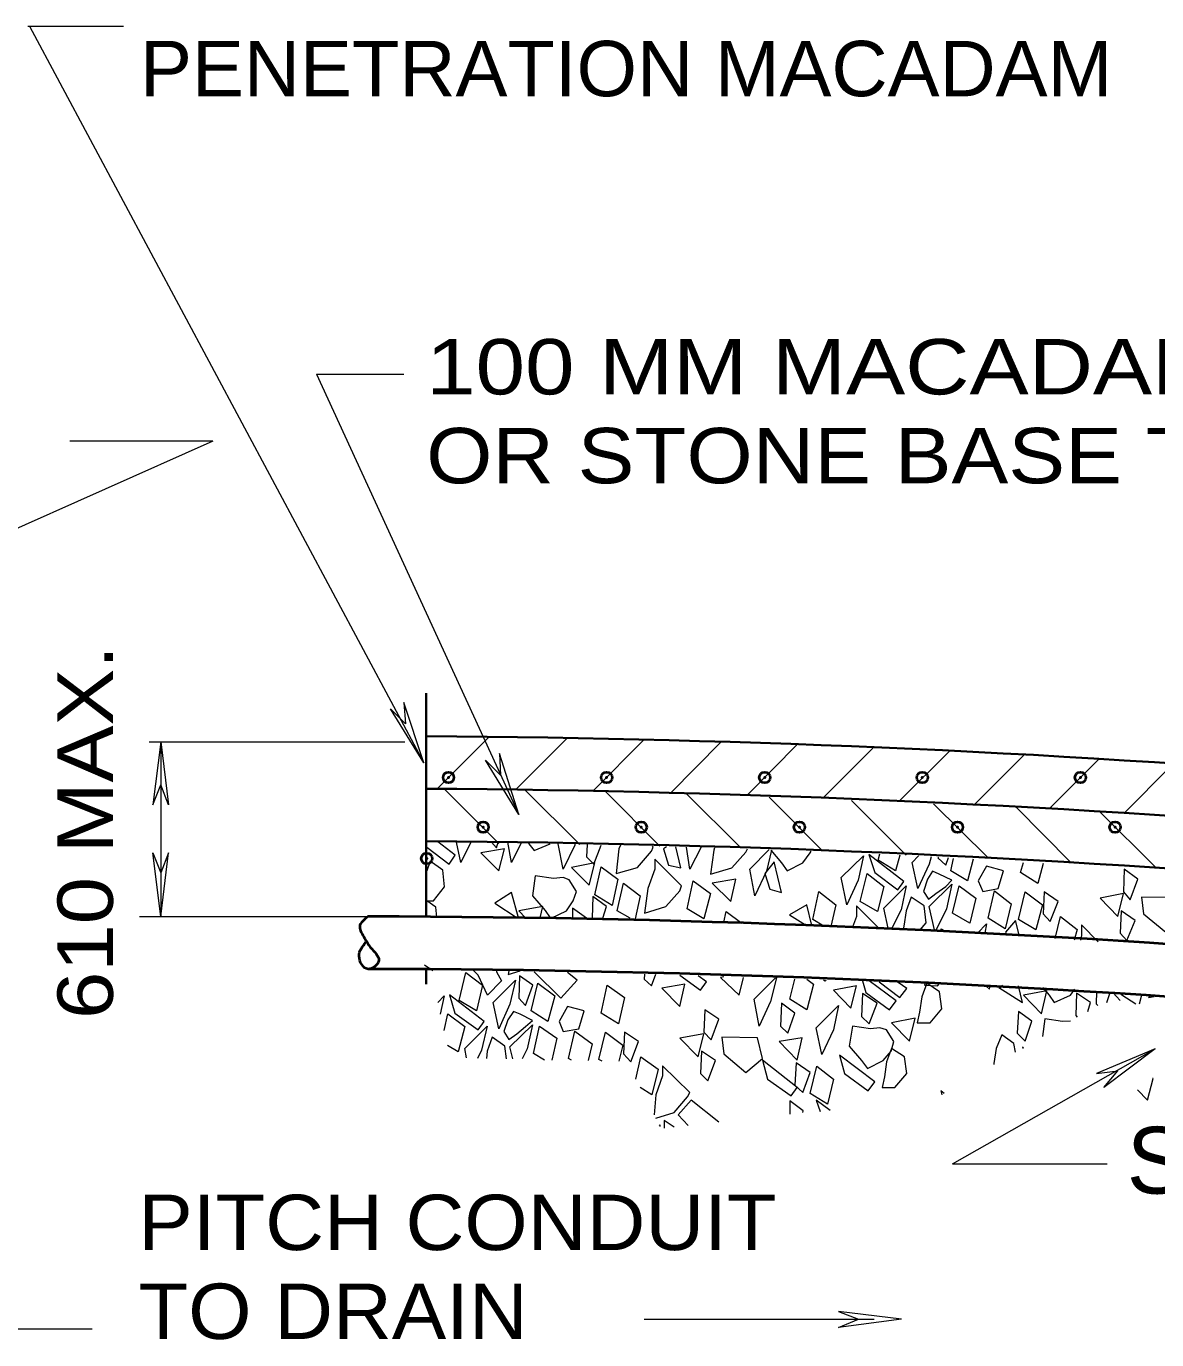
# Model space of a CAD drawing. Extents: x 312583 to 312854, y 144419 to 144597.
# Drawn here: x 312670 to 312685.51, y 144438.89 to 144456.92 of the extents above; entities that cross this region are included whole.
import ezdxf

# ---------------------------------------------------------------- set-up
doc = ezdxf.new("R2010")
doc.units = 0
doc.header["$LTSCALE"] = 0.3
doc.header["$PDMODE"] = 32
doc.header["$PDSIZE"] = 0.15
doc.layers.add('1', color=7, linetype='Continuous', lineweight=40)
doc.layers.add('2', color=7, linetype='Continuous', lineweight=13)

msp = doc.modelspace()

# ---------------------------------------------------------------- linework, layer by layer
at = {"layer": '1', "lineweight": 13}
for p, q in [((312675.6388, 144446.4551), (312676.3365, 144447.1527)), ((312676.7122, 144446.4397), (312677.4252, 144447.1527)), ((312677.7778, 144446.4244), (312678.4755, 144447.1297)), ((312678.8358, 144446.3937), (312679.5335, 144447.0991)), ((312679.8938, 144446.3707), (312680.5838, 144447.0684)), ((312680.9365, 144446.3324), (312681.6265, 144447.0224)), ((312681.9792, 144446.2864), (312682.6692, 144446.9764)), ((312683.0065, 144446.2327), (312683.6965, 144446.9227)), ((312684.0415, 144446.1867), (312684.7162, 144446.8614)), ((312685.0612, 144446.1177), (312685.7052, 144446.7617)), ((312675.7385, 144446.4474), (312676.4822, 144445.7037)), ((312676.8425, 144446.4321), (312677.5938, 144445.6884)), ((312677.9465, 144446.4167), (312678.6902, 144445.6654)), ((312679.0582, 144446.3861), (312679.7942, 144445.6501)), ((312680.1928, 144446.3401), (312680.9212, 144445.6041)), ((312681.3198, 144446.2941), (312682.0712, 144445.5427)), ((312682.4468, 144446.2481), (312683.1905, 144445.5121)), ((312683.5815, 144446.2021), (312684.3328, 144445.4431)), ((312684.7238, 144446.1407), (312685.4982, 144445.3741)), ((312676.8885, 144445.7114), (312676.8962, 144445.6961)), ((312678.7822, 144445.6577), (312678.7438, 144445.6271)), ((312679.9245, 144445.3511), (312680.1928, 144445.6194)), ((312680.2158, 144445.6117), (312680.3615, 144445.4354)), ((312675.4932, 144445.4891), (312675.4932, 144445.4967)), ((312675.5392, 144445.4584), (312675.4932, 144445.3281)), ((312681.6878, 144445.4737), (312681.7108, 144445.5581)), ((312682.1555, 144445.4431), (312682.2398, 144445.5351)), ((312682.6845, 144445.3281), (312682.7228, 144445.4967)), ((312683.6428, 144445.3051), (312683.6812, 144445.4431)), ((312676.4285, 144444.8834), (312676.7352, 144444.6841)), ((312677.7702, 144444.9754), (312677.7625, 144444.6764)), ((312676.7582, 144444.7761), (312676.8502, 144444.6841)), ((312677.1185, 144444.7837), (312677.1875, 144444.6841)), ((312677.4942, 144444.8144), (312677.4942, 144444.6764)), ((312677.6858, 144444.6764), (312677.4942, 144444.8144)), ((312678.2838, 144444.6764), (312678.1075, 144444.7761)), ((312680.4688, 144444.7224), (312680.6912, 144444.5844)), ((312681.3888, 144444.6994), (312681.3352, 144444.5537)), ((312681.8258, 144444.5384), (312681.7645, 144444.8144)), ((312682.4622, 144444.5154), (312682.3855, 144444.8374)), ((312680.9442, 144444.5691), (312680.7908, 144444.6611)), ((312683.4358, 144444.4847), (312683.4512, 144444.4464)), ((312684.4785, 144444.4387), (312684.4632, 144444.3774)), ((312675.5775, 144443.9557), (312675.4625, 144444.0324)), ((312684.9078, 144443.6567), (312685.0075, 144443.5494))]:
    msp.add_line(p, q, dxfattribs=at)
for points in [[(312675.4855, 144445.6577), (312675.4932, 144445.6501), (312675.7998, 144445.4201), (312675.8842, 144445.5427), (312675.6465, 144445.7267)], [(312676.0988, 144445.7191), (312675.9608, 144445.4431), (312675.8995, 144445.7191)], [(312676.3825, 144445.7191), (312676.4515, 144445.6424), (312676.4745, 144445.7191)], [(312676.7888, 144445.7114), (312676.6585, 144445.4431), (312676.6048, 144445.7191)], [(312676.8962, 144445.6961), (312676.9652, 144445.6041), (312677.1875, 144445.6961)], [(312677.5248, 144445.6961), (312677.5248, 144445.6807), (312677.3638, 144445.3511), (312677.2948, 144445.6961)], [(312677.6935, 144445.6884), (312677.6858, 144445.5197), (312677.7855, 144445.4201), (312677.8852, 144445.6807)], [(312678.1535, 144445.6807), (312678.1305, 144445.6271), (312678.0922, 144445.2897), (312678.3835, 144445.3741), (312678.5752, 144445.5964), (312678.5982, 144445.6501), (312678.5905, 144445.6654)], [(312678.7438, 144445.6271), (312678.8128, 144445.4047), (312678.9815, 144445.3664), (312678.9125, 144445.6577)], [(312679.2575, 144445.6501), (312679.1042, 144445.3511), (312679.0582, 144445.6501)], [(312679.4415, 144445.6424), (312679.4338, 144445.6117), (312679.3878, 144445.2821), (312679.6792, 144445.3664), (312679.8708, 144445.5811), (312679.8938, 144445.6271)], [(312680.2235, 144445.6117), (312680.1545, 144445.3204), (312679.9935, 144444.9831), (312679.9245, 144445.3511)], [(312680.3615, 144445.4354), (312680.4382, 144445.3281), (312680.6528, 144445.4354), (312680.7525, 144445.5734), (312680.7678, 144445.5964)], [(312675.4932, 144444.9141), (312675.5852, 144444.9141), (312675.7385, 144445.1057), (312675.7155, 144445.3357), (312675.5392, 144445.4584)], [(312681.9868, 144445.5427), (312681.9255, 144445.3281), (312681.6878, 144445.4737)], [(312682.4162, 144445.5197), (312682.3855, 144445.4201), (312682.2322, 144445.0827), (312682.1555, 144445.4431)], [(312682.5158, 144445.5121), (312682.5082, 144445.5044), (312682.6155, 144445.4047), (312682.6538, 144445.5121)], [(312682.9912, 144445.4891), (312682.9145, 144445.1901), (312682.6845, 144445.3281)], [(312683.9495, 144445.4277), (312683.8805, 144445.1517), (312683.6428, 144445.3051)], [(312677.2028, 144444.6764), (312677.4098, 144444.7761), (312677.5018, 144444.9141), (312677.5478, 144445.0444), (312677.4482, 144445.2054), (312677.3638, 144445.2361), (312677.2335, 144445.2207), (312676.9805, 144445.2591), (312676.9422, 144444.9831), (312677.1185, 144444.7837)], [(312678.1075, 144444.7761), (312678.1918, 144445.1594), (312678.4218, 144444.9831), (312678.3528, 144444.6687)], [(312681.7645, 144444.8144), (312682.0712, 144445.1211), (312682.0022, 144444.7914), (312681.8718, 144444.5307)], [(312682.3855, 144444.8374), (312682.6998, 144445.1441), (312682.6232, 144444.8067), (312682.4852, 144444.5154)], [(312675.6312, 144444.6917), (312675.6158, 144444.8297), (312675.4932, 144444.9141)], [(312676.7505, 144444.6841), (312676.6585, 144445.0291), (312676.4285, 144444.8834)], [(312677.9082, 144444.6764), (312677.9618, 144444.8374), (312677.7702, 144444.9754)], [(312680.7908, 144444.6611), (312680.8752, 144445.0444), (312681.1052, 144444.8604), (312681.0362, 144444.5614)], [(312682.1402, 144444.9677), (312682.0712, 144444.7761), (312682.0405, 144444.5691), (312682.0328, 144444.5231)], [(312682.2628, 144444.5154), (312682.3472, 144444.6151), (312682.3165, 144444.8451), (312682.1402, 144444.9677)], [(312677.0495, 144444.6841), (312677.0878, 144444.8374), (312676.7582, 144444.7761)], [(312679.5718, 144444.6227), (312679.6025, 144444.7684), (312679.8172, 144444.6074)], [(312680.7755, 144444.5767), (312680.7065, 144444.8604), (312680.4688, 144444.7224)], [(312681.6955, 144444.5384), (312681.3888, 144444.8451), (312681.3888, 144444.6994)], [(312684.1182, 144444.4004), (312684.1872, 144444.6994), (312684.4172, 144444.5231), (312684.3788, 144444.3774)], [(312682.5542, 144444.5077), (312682.5542, 144444.5307), (312682.5925, 144444.5077)], [(312683.0525, 144444.4694), (312683.1752, 144444.5997), (312683.1522, 144444.4694)], [(312683.6275, 144444.4311), (312683.5738, 144444.6457), (312683.4358, 144444.4847)], [(312684.7085, 144444.3544), (312684.4785, 144444.5844), (312684.4785, 144444.4387)]]:
    msp.add_lwpolyline(points, dxfattribs=at)
for points in [[(312676.2368, 144445.5734), (312676.4822, 144445.3281), (312676.5588, 144445.6271)], [(312677.4788, 144445.3741), (312677.7242, 144445.1287), (312677.8008, 144445.4354)], [(312678.6212, 144445.3511), (312678.5292, 144445.0827), (312678.4832, 144444.7454), (312678.7745, 144444.8374), (312678.9662, 144445.0521), (312678.9892, 144445.1211), (312678.6212, 144445.4891)], [(312680.1315, 144445.2897), (312680.2005, 144445.0751), (312680.3615, 144445.0291), (312680.2618, 144445.4507)], [(312681.1818, 144445.2361), (312681.4885, 144445.5351), (312681.4118, 144445.1977), (312681.2585, 144444.8604)], [(312681.6418, 144445.3051), (312681.9562, 144445.0674), (312682.0405, 144445.1824), (312681.5575, 144445.5504)], [(312677.8008, 144444.9984), (312677.8852, 144445.3817), (312678.1152, 144445.2131), (312678.0385, 144444.8527)], [(312681.4425, 144444.9064), (312681.5345, 144445.2897), (312681.7645, 144445.1134), (312681.6802, 144444.7684)], [(312682.5235, 144445.2821), (312682.4315, 144445.3204), (312682.3625, 144445.2131), (312682.3088, 144445.0444), (312682.3778, 144444.9371), (312682.4775, 144445.0137), (312682.6155, 144445.1134), (312682.6998, 144445.1977)], [(312683.1752, 144445.3894), (312683.0602, 144445.1901), (312683.1215, 144445.0444), (312683.3362, 144445.0827), (312683.4052, 144445.3281)], [(312685.0612, 144445.3511), (312685.0535, 144445.0367), (312685.1455, 144444.9294), (312685.2528, 144445.2131)], [(312679.0658, 144444.8067), (312679.1502, 144445.1901), (312679.3878, 144445.0137), (312679.2958, 144444.6687)], [(312679.4108, 144445.1594), (312679.6638, 144444.9064), (312679.7328, 144445.2131)], [(312682.7075, 144444.7454), (312682.7995, 144445.1211), (312683.0295, 144444.9524), (312682.9452, 144444.6074)], [(312683.1982, 144444.6764), (312683.2825, 144445.0521), (312683.5125, 144444.8757), (312683.4282, 144444.5307)], [(312683.6122, 144444.6611), (312683.7042, 144445.0367), (312683.9418, 144444.8604), (312683.8498, 144444.5154)], [(312683.9648, 144445.0367), (312683.9495, 144444.7377), (312684.0492, 144444.6304), (312684.1565, 144444.9064)], [(312684.7315, 144444.9524), (312684.9768, 144444.6994), (312685.0535, 144445.0137)], [(312685.3295, 144444.7377), (312685.6362, 144444.4847), (312685.8508, 144444.6764), (312685.7895, 144444.9601), (312685.2988, 144444.9677)], [(312685.0228, 144444.7761), (312685.0075, 144444.4694), (312685.0995, 144444.3697), (312685.2145, 144444.6457)]]:
    msp.add_lwpolyline(points, close=True, dxfattribs=at)
at = {"layer": '1'}
for p in [(312675.7922, 144446.6084), (312677.9618, 144446.6084), (312680.1315, 144446.6084), (312682.2935, 144446.6084), (312684.4632, 144446.6084), (312676.2675, 144445.9261), (312678.4372, 144445.9261), (312680.6068, 144445.9261), (312682.7765, 144445.9261), (312684.9385, 144445.9261), (312675.4932, 144445.4967)]:
    msp.add_point(p, dxfattribs=at)
at = {"layer": '2'}
for p, q in [((312670.0192, 144456.9201), (312671.3302, 144456.9201)), ((312670.0422, 144456.9201), (312675.4548, 144446.8077)), ((312673.9828, 144452.1437), (312675.1788, 144452.1437)), ((312673.9828, 144452.1437), (312676.7582, 144446.1024)), ((312672.5568, 144451.2237), (312661.0875, 144446.1177)), ((312672.5568, 144451.2237), (312670.5942, 144451.2237)), ((312675.1788, 144447.6357), (312675.2018, 144447.3444)), ((312675.4548, 144446.8077), (312675.1788, 144447.6357)), ((312674.9948, 144447.5514), (312675.2018, 144447.3444)), ((312675.4548, 144446.8077), (312674.9948, 144447.5514)), ((312671.6828, 144447.0991), (312675.1942, 144447.0991)), ((312671.8438, 144447.0991), (312671.7365, 144446.2327)), ((312671.8438, 144447.0991), (312671.8438, 144444.6994)), ((312671.8438, 144447.0991), (312671.9512, 144446.2327)), ((312676.4898, 144446.9381), (312676.5052, 144446.6391)), ((312676.7582, 144446.1024), (312676.4898, 144446.9381)), ((312676.2982, 144446.8461), (312676.5052, 144446.6391)), ((312676.7582, 144446.1024), (312676.2982, 144446.8461)), ((312671.7365, 144446.2327), (312671.8438, 144446.5087)), ((312671.9512, 144446.2327), (312671.8438, 144446.5087)), ((312671.7365, 144445.5734), (312671.8438, 144445.2974)), ((312671.8438, 144444.6994), (312671.7365, 144445.5734)), ((312671.9512, 144445.5734), (312671.8438, 144445.2974)), ((312671.8438, 144444.6994), (312671.9512, 144445.5734)), ((312671.5525, 144444.6994), (312675.1635, 144444.6994)), ((312679.5718, 144443.8714), (312679.5258, 144443.8637)), ((312679.9858, 144443.5647), (312680.2772, 144443.8561)), ((312680.4765, 144443.5647), (312680.5455, 144443.8407)), ((312681.4732, 144443.8177), (312681.5192, 144443.6567)), ((312683.9418, 144443.7257), (312684.0338, 144443.6184)), ((312684.8235, 144443.5187), (312684.8695, 144443.6567)), ((312685.0305, 144443.6184), (312685.0305, 144443.6414)), ((312685.2222, 144443.4957), (312685.0305, 144443.6184)), ((312685.2988, 144443.6184), (312685.2682, 144443.4957)), ((312676.0375, 144442.7597), (312676.0145, 144442.8901)), ((312676.6738, 144442.7444), (312676.6355, 144442.9131)), ((312682.7075, 144441.3031), (312685.4905, 144442.8824)), ((312683.6658, 144442.9054), (312683.6735, 144442.8901)), ((312683.6812, 144442.8977), (312683.6658, 144442.9054)), ((312685.4905, 144442.8824), (312684.6855, 144442.5451)), ((312685.4905, 144442.8824), (312684.7852, 144442.3534)), ((312677.1108, 144442.7291), (312676.9575, 144442.8211)), ((312677.4788, 144442.7291), (312677.4405, 144442.7521)), ((312677.9005, 144442.7137), (312677.8545, 144442.7367)), ((312684.6855, 144442.5451), (312684.9768, 144442.5834)), ((312684.7852, 144442.3534), (312684.9768, 144442.5834)), ((312679.5028, 144441.8781), (312679.1195, 144442.1771)), ((312680.4765, 144442.1694), (312680.4765, 144441.9854)), ((312678.7515, 144441.9011), (312678.7515, 144441.7937)), ((312678.8895, 144441.8091), (312678.7515, 144441.9011)), ((312682.7075, 144441.3031), (312684.8312, 144441.3031)), ((312681.1435, 144439.2791), (312681.4195, 144439.1717)), ((312682.0098, 144439.1717), (312681.1435, 144439.2791)), ((312678.4755, 144439.1717), (312681.6342, 144439.1717)), ((312681.1435, 144439.0567), (312681.4195, 144439.1717)), ((312682.0098, 144439.1717), (312681.1435, 144439.0567)), ((312668.9305, 144439.0414), (312670.9008, 144439.0414))]:
    msp.add_line(p, q, dxfattribs=at)
at = {"layer": '2', "lineweight": 35}
for p, q in [((312675.4855, 144444.6994), (312675.4855, 144447.7661)), ((312675.4855, 144443.7717), (312675.4855, 144443.9787)), ((312683.3975, 144443.7487), (312683.3438, 144443.7257))]:
    msp.add_line(p, q, dxfattribs=at)
at = {"layer": '2'}
for points in [[(312676.3288, 144443.6184), (312676.1985, 144443.8944), (312676.1295, 144443.9634)], [(312676.4515, 144443.9557), (312676.4515, 144443.9404), (312676.5205, 144443.8177), (312676.3288, 144443.6184)], [(312676.6202, 144443.9557), (312676.6125, 144443.9021), (312676.7735, 144443.9557)], [(312676.9652, 144443.9404), (312677.3332, 144443.5801), (312677.5555, 144443.8254), (312677.4252, 144443.9327)], [(312678.4832, 144443.9097), (312678.4755, 144443.8407), (312678.5752, 144443.7487), (312678.6365, 144443.9097)], [(312678.9662, 144443.8944), (312679.2498, 144443.6874), (312679.3342, 144443.8024), (312679.2192, 144443.8867)], [(312679.5258, 144443.8637), (312679.7788, 144443.6184), (312679.8402, 144443.8637)], [(312680.2925, 144443.8561), (312680.2082, 144443.5341), (312680.0548, 144443.1967), (312679.9858, 144443.5647)], [(312680.7065, 144443.8407), (312680.7985, 144443.7717), (312680.7065, 144443.4191), (312680.4765, 144443.5647)], [(312680.9365, 144443.8331), (312680.9595, 144443.8177), (312680.9748, 144443.8254)], [(312681.5192, 144443.6567), (312681.8412, 144443.4191), (312681.9332, 144443.5417), (312681.5652, 144443.8177)], [(312681.7032, 144443.8024), (312681.9868, 144443.5877), (312682.0788, 144443.7104), (312681.9638, 144443.7947)], [(312682.3318, 144443.7871), (312682.3242, 144443.7564), (312682.5005, 144443.7487), (312682.5312, 144443.7794)], [(312675.6465, 144443.5187), (312675.7308, 144443.6107), (312675.6772, 144443.3577)], [(312683.1752, 144443.7411), (312683.2135, 144443.7027), (312683.2212, 144443.7334)], [(312683.3438, 144443.7257), (312683.6658, 144443.5187), (312683.6122, 144443.7487)], [(312684.0338, 144443.6184), (312684.1028, 144443.5187), (312684.3252, 144443.6184), (312684.3865, 144443.7027)], [(312684.4095, 144443.6491), (312684.4018, 144443.3424), (312684.4172, 144443.3194)], [(312684.5628, 144443.3961), (312684.6012, 144443.5187), (312684.4095, 144443.6491)], [(312684.6855, 144443.6721), (312684.6778, 144443.5034), (312684.7008, 144443.4804)], [(312685.4138, 144443.6107), (312685.3985, 144443.5877), (312685.4752, 144443.6031)], [(312675.7308, 144443.1354), (312675.7845, 144443.3654), (312676.0145, 144443.1891), (312675.9225, 144442.8441), (312675.7768, 144442.9284)], [(312684.3252, 144443.2657), (312684.2178, 144443.2581), (312683.9725, 144443.2964), (312683.9418, 144443.0511)], [(312676.0145, 144442.8901), (312676.3212, 144443.1967), (312676.2445, 144442.8671), (312676.1908, 144442.7521)], [(312676.6355, 144442.9131), (312676.9422, 144443.2121), (312676.8732, 144442.8824), (312676.8042, 144442.7444)], [(312676.9575, 144442.8211), (312677.0418, 144443.1967), (312677.2795, 144443.0281), (312677.2105, 144442.7291)], [(312677.4405, 144442.7521), (312677.5248, 144443.1277), (312677.7625, 144442.9514), (312677.7088, 144442.7214)], [(312677.8545, 144442.7367), (312677.9465, 144443.1124), (312678.1842, 144442.9361), (312678.1305, 144442.7137)], [(312683.3822, 144443.0741), (312683.3055, 144442.8901), (312683.2748, 144442.6831), (312683.2748, 144442.6677)], [(312683.5738, 144442.8364), (312683.5508, 144442.9591), (312683.3822, 144443.0741)], [(312676.3902, 144443.0434), (312676.3212, 144442.8517), (312676.3135, 144442.7521)], [(312676.5895, 144442.7444), (312676.5665, 144442.9207), (312676.3902, 144443.0434)], [(312678.3605, 144442.4684), (312678.4295, 144442.7751), (312678.6672, 144442.6064), (312678.5828, 144442.2537), (312678.4218, 144442.3534)], [(312678.6365, 144441.9317), (312678.8895, 144442.0084), (312679.0735, 144442.2231), (312679.1042, 144442.2844), (312678.7285, 144442.6524), (312678.7285, 144442.5144)], [(312678.7285, 144442.5144), (312678.6365, 144442.2537), (312678.6135, 144441.9777)], [(312685.2452, 144442.3227), (312685.3832, 144442.1771), (312685.4598, 144442.4761), (312685.4522, 144442.4761)], [(312679.1195, 144442.1771), (312678.9432, 144441.9777), (312679.0812, 144441.8321)], [(312680.6528, 144442.0084), (312680.6605, 144442.0314), (312680.4765, 144442.1694)], [(312681.0285, 144442.0391), (312680.8368, 144442.1771), (312680.8905, 144442.0237)], [(312682.5925, 144442.2691), (312682.5465, 144442.3074), (312682.5618, 144442.2537)], [(312678.6825, 144441.8321), (312678.6902, 144441.8397), (312678.6902, 144441.8167)]]:
    msp.add_lwpolyline(points, dxfattribs=at)
for points in [[(312675.9378, 144443.5494), (312676.0298, 144443.9327), (312676.2598, 144443.7564), (312676.1755, 144443.4037)], [(312676.4055, 144443.5187), (312676.7122, 144443.8254), (312676.6355, 144443.4957), (312676.4822, 144443.1584)], [(312676.7658, 144443.8867), (312676.7582, 144443.5801), (312676.8502, 144443.4804), (312676.9498, 144443.7564)], [(312676.9268, 144443.4037), (312677.0188, 144443.7871), (312677.2488, 144443.6107), (312677.1568, 144443.2581)], [(312682.3548, 144443.7871), (312682.2858, 144443.5954), (312682.2552, 144443.3884), (312682.2245, 144443.2427), (312682.4008, 144443.2427), (312682.5618, 144443.4344), (312682.5312, 144443.6644)], [(312675.8765, 144443.3731), (312676.1985, 144443.1431), (312676.2828, 144443.2581), (312675.8075, 144443.6261)], [(312677.8852, 144443.3731), (312677.9695, 144443.7564), (312678.2072, 144443.5877), (312678.1228, 144443.2274)], [(312678.7208, 144443.7181), (312678.9662, 144443.4651), (312679.0352, 144443.7717)], [(312681.0745, 144443.6874), (312681.3122, 144443.4421), (312681.3888, 144443.7487)], [(312681.4732, 144443.6414), (312681.4578, 144443.3271), (312681.5652, 144443.2274), (312681.6725, 144443.5111)], [(312683.6812, 144443.6184), (312683.9265, 144443.3654), (312684.0032, 144443.6797)], [(312677.4252, 144443.4651), (312677.3102, 144443.2581), (312677.3638, 144443.1201), (312677.5785, 144443.1584), (312677.6552, 144443.4037)], [(312680.3615, 144443.5111), (312680.3462, 144443.1967), (312680.4458, 144443.0971), (312680.5455, 144443.3731)], [(312680.8368, 144443.1737), (312681.1435, 144443.4804), (312681.0745, 144443.1431), (312680.9135, 144442.8057)], [(312676.7735, 144443.3577), (312676.6815, 144443.3961), (312676.6048, 144443.2811), (312676.5512, 144443.1201), (312676.6202, 144443.0127), (312676.7275, 144443.0894), (312676.8502, 144443.1891), (312676.9422, 144443.2734)], [(312679.3112, 144443.4191), (312679.2958, 144443.1124), (312679.3955, 144443.0051), (312679.5028, 144443.2887)], [(312681.8718, 144443.2427), (312682.1172, 144442.9897), (312682.1938, 144443.3041)], [(312683.6122, 144443.3961), (312683.5968, 144443.0971), (312683.7042, 144442.9897), (312683.7962, 144443.2657)], [(312678.2072, 144443.1124), (312678.1918, 144442.8134), (312678.2915, 144442.7061), (312678.3988, 144442.9821)], [(312678.9662, 144443.0281), (312679.2192, 144442.7751), (312679.2958, 144443.0894)], [(312681.4578, 144442.7214), (312681.5422, 144442.6141), (312681.7568, 144442.7214), (312681.8642, 144442.8517), (312681.9025, 144442.9821), (312681.8028, 144443.1431), (312681.7108, 144443.1737), (312681.5805, 144443.1584), (312681.3352, 144443.1967), (312681.2892, 144442.9207)], [(312679.5718, 144442.8134), (312679.8708, 144442.5604), (312680.1008, 144442.7521), (312680.0318, 144443.0357), (312679.5412, 144443.0434)], [(312680.3308, 144442.9821), (312680.5762, 144442.7291), (312680.6452, 144443.0357)], [(312681.8718, 144442.8901), (312681.8028, 144442.7061), (312681.7722, 144442.4991), (312681.7415, 144442.3534), (312681.9178, 144442.3534), (312682.0788, 144442.5451), (312682.0482, 144442.7751)], [(312679.2652, 144442.8517), (312679.2498, 144442.5451), (312679.3495, 144442.4454), (312679.4568, 144442.7214)], [(312680.1698, 144442.4684), (312680.4918, 144442.2384), (312680.5762, 144442.3534), (312680.1008, 144442.7291)], [(312681.2278, 144442.5451), (312681.5498, 144442.3074), (312681.6418, 144442.4301), (312681.1588, 144442.7981)], [(312680.5608, 144442.6907), (312680.5455, 144442.3841), (312680.6528, 144442.2844), (312680.7525, 144442.5604)], [(312680.7525, 144442.2691), (312680.8445, 144442.6447), (312681.0745, 144442.4684), (312680.9902, 144442.1234)]]:
    msp.add_lwpolyline(points, close=True, dxfattribs=at)
at = {"layer": '2', "lineweight": 35}
for radius, start, end in [(171.3086, 80.70018, 89.61922), (170.5881, 80.66055, 89.61762), (169.8675, 80.62058, 89.61599)]:
    msp.add_arc((312674.349, 144275.8703), radius, start, end, dxfattribs=at)
at = {"layer": '2', "lineweight": 40}
for radius in [168.8299, 168.1094]:
    msp.add_arc((312674.349, 144275.8703), radius, 80.56235, 89.88555, dxfattribs=at)
msp.add_spline([(312674.6882, 144444.6994), (312674.5732, 144444.5614), (312674.6422, 144444.4004), (312674.7188, 144444.2777), (312674.8338, 144444.0937), (312674.6882, 144443.9787), (312674.5655, 144444.1551), (312674.6575, 144444.3467)], degree=3, dxfattribs=at)

# ---------------------------------------------------------------- texts
at = {"layer": '2'}
for s, width, p in [('PENETRATION MACADAM', 1.05, (312671.5602, 144455.9597)), ('100 MM MACADAM  BASE', 1.2, (312675.4855, 144451.8667)), ('OR STONE BASE TYPICAL', 1.15, (312675.4855, 144450.6467)), ('PITCH CONDUIT', 1.1, (312671.5372, 144440.1214)), ('TO DRAIN', 1.1, (312671.5372, 144438.9014))]:
    msp.add_text(s, height=0.76, dxfattribs=dict(at, width=width)).set_placement(p)
at = {"layer": '2', "width": 1.15}
msp.add_text('610 MAX.', height=0.76, rotation=90, dxfattribs=at).set_placement((312671.1865, 144443.2927))
at = {"layer": '2'}
msp.add_text('SUBBASE', height=0.9165, dxfattribs=at).set_placement((312685.0995, 144440.8967))

doc.saveas('drawing.dxf')
